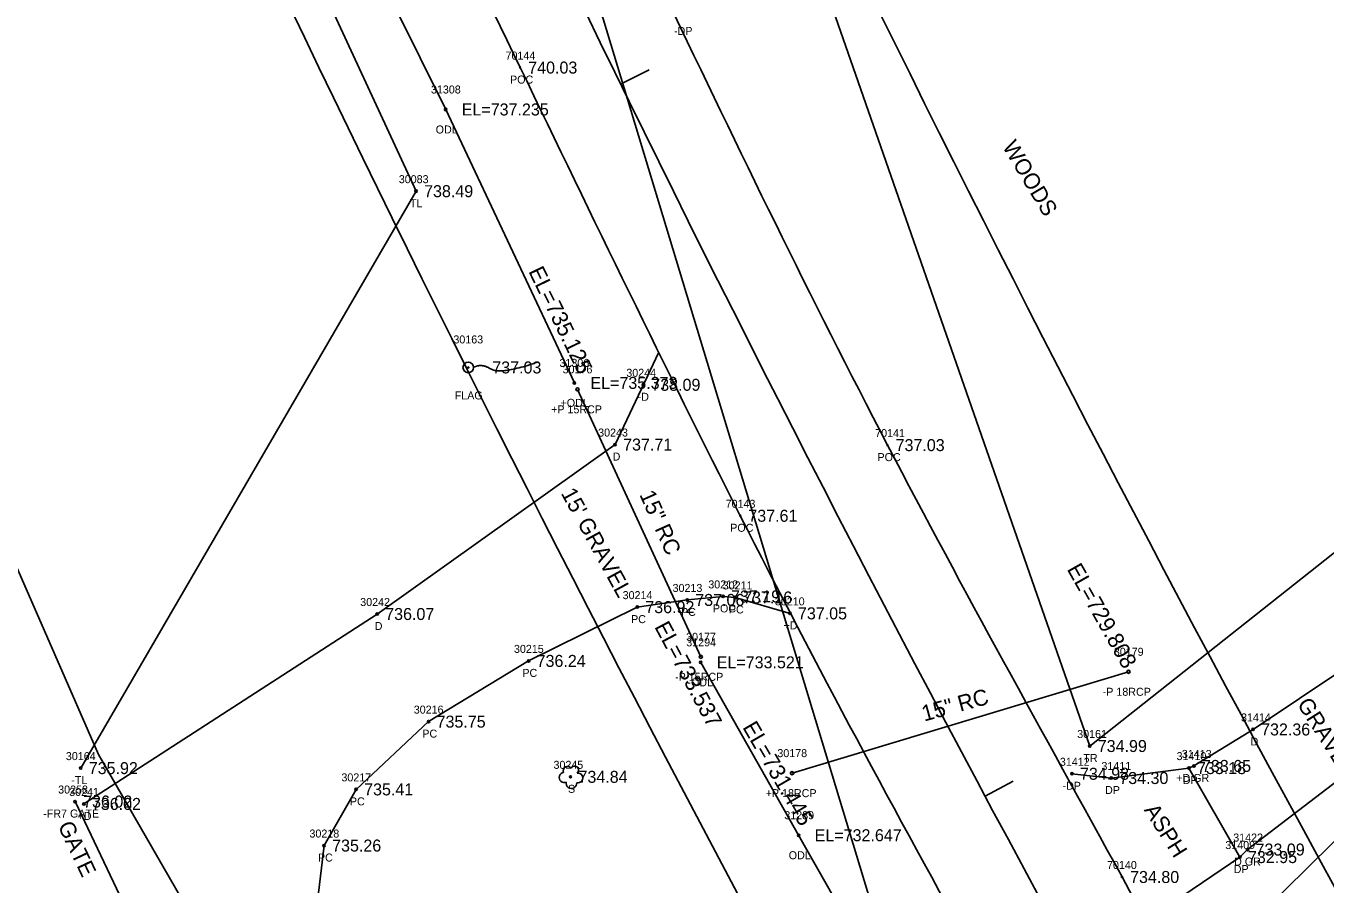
# Model space of a CAD drawing. Extents: x 1375131 to 1378678, y 999028 to 1004053.
# Drawn here: x 1376815.5 to 1376977.9, y 1002369.5 to 1002476.7 of the extents above; entities that cross this region are included whole.
import ezdxf

# ---------------------------------------------------------------- set-up
doc = ezdxf.new("R2010")
doc.units = 0
for name, color, linetype in [('RD_EX_BldgApp_txCode', 7, 'Continuous'), ('RD_EX_DR_Pipe', 7, 'Continuous'), ('RD_EX_DR_Pipe_txCode', 7, 'Continuous'), ('RD_EX_Driveway', 7, 'Continuous'), ('RD_EX_Driveway_txCode', 7, 'Continuous'), ('RD_EX_DV_Prop', 7, 'Continuous'), ('RD_EX_Fence_Other', 7, 'Continuous'), ('RD_EX_Fence_Other_txCode', 7, 'Continuous'), ('RD_EX_H2O', 7, 'Continuous'), ('RD_EX_H2O_txCode', 7, 'Continuous'), ('RD_EX_Road', 7, 'Continuous'), ('RD_EX_Road_txCode', 7, 'Continuous'), ('RD_EX_RW', 7, 'Continuous'), ('RD_EX_SU_Elec', 7, 'Continuous'), ('RD_EX_SU_Telecom', 7, 'Continuous'), ('RD_EX_TX_BldgApp_ELEV', 7, 'Continuous'), ('RD_EX_TX_Driveway_ELEV', 7, 'Continuous'), ('RD_EX_TX_Fence_Other_ELEV', 7, 'Continuous'), ('RD_EX_TX_H2O_ELEV', 7, 'Continuous'), ('RD_EX_TX_Road_ELEV', 7, 'Continuous'), ('RD_EX_TX_VEG_ELEV', 7, 'Continuous'), ('RD_EX_VEG', 7, 'Continuous'), ('RD_EX_VEG_txCode', 7, 'Continuous'), ('RD_HC_Cl', 7, 'Continuous'), ('RD_HC_Data_Tic', 7, 'Continuous'), ('RD_SMD_Locator', 7, 'Continuous'), ('RD_TX_Drainage', 7, 'Continuous'), ('RD_TX_Misc2', 7, 'Continuous'), ('RD_TX_Pipe_ElevEX', 7, 'Continuous')]:
    doc.layers.add(name, color=color, linetype=linetype)

msp = doc.modelspace()

# ---------------------------------------------------------------- linework, layer by layer
at = {"layer": 'RD_EX_DR_Pipe'}
for p, q in [((1376884.43, 1002431.29), (1376899.84, 1002397.86)), ((1376911.24, 1002383.32), (1376953.27, 1002395.99))]:
    msp.add_line(p, q, dxfattribs=at)
at = {"layer": 'RD_EX_Driveway'}
for points in [[(1376822.75, 1002379.47), (1376859.4, 1002403.21), (1376889.13, 1002424.39), (1376894.58, 1002435.93)], [(1376960.83, 1002383.95), (1376961.45, 1002384.22), (1376968.84, 1002388.78), (1376986.2, 1002400.38), (1377021.48, 1002432.82)], [(1377039.21, 1002432.48), (1377014.55, 1002411.97), (1376990.81, 1002391.11), (1376968.15, 1002373.77), (1376967.2, 1002372.83)], [(1376911, 1002403.28), (1376904.12, 1002405.28), (1376902.61, 1002405.41), (1376898.14, 1002404.97), (1376891.9, 1002404.07), (1376878.32, 1002397.35), (1376865.82, 1002389.76), (1376856.77, 1002381.29), (1376852.77, 1002374.27), (1376851.72, 1002365.55), (1376852.45, 1002354.79), (1376854.03, 1002345.76), (1376868.77, 1002323.94), (1376875.45, 1002322.88), (1376882.22, 1002322.93), (1376889.24, 1002324.18), (1376897.79, 1002328.76), (1376900.27, 1002330.09), (1376914.86, 1002340.55), (1376927.38, 1002353.05), (1376934.4, 1002359.99)], [(1376956.44, 1002362.93), (1376956.57, 1002365.63), (1376967.2, 1002372.83), (1376960.83, 1002383.95), (1376951.12, 1002382.71), (1376946.21, 1002383.24)]]:
    msp.add_lwpolyline(points, dxfattribs=at)
at = {"layer": 'RD_EX_DV_Prop'}
msp.add_lwpolyline([(1376724.42, 1002117.06), (1376637.57, 1002230.63), (1376389.38, 1002558.79), (1376664.3, 1002769.81), (1376707.09, 1002654.77), (1376824.56, 1002385.67), (1376921.89, 1002216.69), (1376947.76, 1002098.6)], dxfattribs=at)
at = {"layer": 'RD_EX_Fence_Other'}
msp.add_line((1376828.04, 1002366.35), (1376821.66, 1002379.77), dxfattribs=at)
at = {"layer": 'RD_EX_H2O'}
for points in [[(1376884.04, 1002432.1), (1376867.96, 1002466.27), (1376845.47, 1002511.58), (1376827.22, 1002560.38), (1376806.48, 1002611.18), (1376788.41, 1002651.65), (1376772.82, 1002694.38), (1376753.28, 1002747.21), (1376736.65, 1002792.89), (1376719.2, 1002838.91), (1376701.08, 1002887.18), (1376684.58, 1002932.85), (1376667.2, 1002979.87)], [(1376924.34, 1002353.93), (1376912.06, 1002375.56), (1376899.82, 1002397.17)]]:
    msp.add_lwpolyline(points, dxfattribs=at)
at = {"layer": 'RD_EX_Road'}
for points in [[(1377013.31, 1002264.91), (1376982.81, 1002315.68), (1376952.47, 1002370.34), (1376923.17, 1002424.32), (1376895.64, 1002480.03), (1376870.11, 1002535.05), (1376846.33, 1002588.86), (1376822.29, 1002645.03), (1376786.56, 1002736.46)], [(1376994.75, 1002253.91), (1376964.91, 1002306.46), (1376934.4, 1002359.99), (1376904.77, 1002415.49), (1376877.27, 1002471.51), (1376851.04, 1002526.89), (1376827.48, 1002581.62), (1376804.19, 1002637.82), (1376768.46, 1002728.84)]]:
    msp.add_spline(points, degree=3, dxfattribs=at)
at = {"layer": 'RD_EX_RW'}
for radius in [2767, 2833]:
    msp.add_arc((1379404.86, 1003700.11), radius, 200.26995, 211.13117, dxfattribs=at)
at = {"layer": 'RD_EX_SU_Elec'}
for p, q in [((1376829.24, 1002670.59), (1376932.6, 1002329.07)), ((1376932.6, 1002329.07), (1377119.53, 1002513.39))]:
    msp.add_line(p, q, dxfattribs=at)
at = {"layer": 'RD_EX_SU_Telecom'}
msp.add_circle((1376870.78, 1002434.03), 0.66, dxfattribs=at)
msp.add_open_spline([(1376871.44, 1002434.03), (1376872.44, 1002434.58), (1376874.78, 1002433.1), (1376879.46, 1002434.69)], degree=2, dxfattribs=at)
at = {"layer": 'RD_EX_VEG'}
for points in [[(1376822.36, 1002383.95), (1376864.26, 1002456.06), (1376837.78, 1002513.31), (1376810.93, 1002575.39), (1376788.96, 1002632.35), (1376765.83, 1002686.46), (1376747.01, 1002742.76), (1376726.94, 1002799.92), (1376678.97, 1002911.63), (1376653.9, 1002974.89)], [(1377016.16, 1002440.33), (1376948.43, 1002386.71), (1376912.58, 1002489.62), (1376961.85, 1002505.13), (1376995.25, 1002514.98)]]:
    msp.add_lwpolyline(points, dxfattribs=at)
msp.add_circle((1376883.55, 1002382.86), 0.125, dxfattribs=at)
for centre, radius, start, end in [((1376883.19, 1002383.63), 0.542, 34.9763, 204.756), ((1376884.07, 1002383.71), 0.497, 308.7626, 152.0467), ((1376882.77, 1002382.78), 0.628, 96.4518, 294.734), ((1376884.47, 1002382.72), 0.609, 256.5667, 98.1046), ((1376883.67, 1002382.06), 0.659, 166.8827, 5.7589)]:
    msp.add_arc(centre, radius, start, end, dxfattribs=at)
at = {"layer": 'RD_HC_Cl'}
msp.add_arc((1379404.86, 1003700.11), 2800, 200.26995, 211.13117, dxfattribs=at)
at = {"layer": 'RD_HC_Data_Tic'}
for p, q in [((1376889.81, 1002469.45), (1376893.4, 1002471.21)), ((1376935.35, 1002380.44), (1376938.88, 1002382.32))]:
    msp.add_line(p, q, dxfattribs=at)
at = {"layer": 'RD_SMD_Locator'}
for centre, radius in [((1376877.27, 1002471.51), 0.075), ((1376867.96, 1002466.27), 0.15), ((1376864.26, 1002456.06), 0.15), ((1376870.78, 1002434.03), 0.075), ((1376884.04, 1002432.1), 0.15), ((1376884.43, 1002431.29), 0.2), ((1376892.65, 1002431.86), 0.15), ((1376889.13, 1002424.39), 0.15), ((1376923.17, 1002424.32), 0.075), ((1376904.77, 1002415.49), 0.075), ((1376898.14, 1002404.97), 0.15), ((1376902.61, 1002405.41), 0.15), ((1376904.12, 1002405.28), 0.15), ((1376891.9, 1002404.07), 0.15), ((1376910.97, 1002403.29), 0.15), ((1376859.4, 1002403.21), 0.15), ((1376878.32, 1002397.35), 0.15), ((1376899.84, 1002397.86), 0.2), ((1376899.82, 1002397.17), 0.15), ((1376953.27, 1002395.99), 0.2), ((1376865.82, 1002389.76), 0.15), ((1376968.84, 1002388.78), 0.15), ((1376948.43, 1002386.71), 0.15), ((1376822.36, 1002383.95), 0.15), ((1376960.83, 1002383.95), 0.15), ((1376961.45, 1002384.22), 0.15), ((1376883.55, 1002382.86), 0.075), ((1376911.24, 1002383.32), 0.2), ((1376946.21, 1002383.24), 0.15), ((1376951.12, 1002382.71), 0.15), ((1376856.77, 1002381.29), 0.15), ((1376821.66, 1002379.77), 0.15), ((1376822.75, 1002379.47), 0.15), ((1376852.77, 1002374.27), 0.15), ((1376912.06, 1002375.56), 0.15), ((1376967.2, 1002372.83), 0.15), ((1376968.15, 1002373.77), 0.15), ((1376952.47, 1002370.34), 0.075)]:
    msp.add_circle(centre, radius, dxfattribs=at)

# ---------------------------------------------------------------- texts
at = {"layer": 'RD_EX_BldgApp_txCode'}
for s, p in [('30163', (1376868.92, 1002437.03)), ('FLAG', (1376869.09, 1002430.03))]:
    msp.add_text(s, height=1, dxfattribs=at).set_placement(p)
at = {"layer": 'RD_EX_DR_Pipe_txCode'}
for s, p in [('30176', (1376882.57, 1002433.29)), ('+P 15RCP', (1376881.13, 1002428.29)), ('30177', (1376898, 1002399.86)), ('30179', (1376951.44, 1002397.99)), ('-P 15RCP', (1376896.62, 1002394.86)), ('-P 18RCP', (1376950.05, 1002392.99)), ('30178', (1376909.4, 1002385.32)), ('+P 18RCP', (1376907.94, 1002380.32))]:
    msp.add_text(s, height=1, dxfattribs=at).set_placement(p)
at = {"layer": 'RD_EX_Driveway_txCode'}
for s, p in [('-DP', (1376896.49, 1002475.59)), ('30244', (1376890.53, 1002432.86)), ('-D', (1376891.94, 1002429.86)), ('30243', (1376887.01, 1002425.39)), ('D', (1376888.82, 1002422.39)), ('30213', (1376896.31, 1002405.97)), ('30212', (1376900.77, 1002406.41)), ('30211', (1376902.57, 1002406.28)), ('30242', (1376857.28, 1002404.21)), ('30214', (1376890.07, 1002405.07)), ('30210', (1376909.09, 1002404.29)), ('PC', (1376897.36, 1002402.97)), ('POC', (1376901.34, 1002403.41)), ('PC', (1376903.34, 1002403.28)), ('D', (1376859.09, 1002401.21)), ('PC', (1376891.12, 1002402.07)), ('+D', (1376910.17, 1002401.29)), ('30215', (1376876.49, 1002398.35)), ('PC', (1376877.54, 1002395.35)), ('30216', (1376863.97, 1002390.76)), ('31414', (1376967.33, 1002389.78)), ('PC', (1376865.04, 1002387.76)), ('D', (1376968.53, 1002386.78)), ('31410', (1376959.28, 1002384.95)), ('31413', (1376959.94, 1002385.22)), ('31412', (1376944.7, 1002384.24)), ('31411', (1376949.89, 1002383.71)), ('30217', (1376854.93, 1002382.29)), ('+D GR', (1376959.24, 1002382.22)), ('DP', (1376960.05, 1002381.95)), ('30241', (1376820.92, 1002380.47)), ('-DP', (1376945.02, 1002381.24)), ('DP', (1376950.34, 1002380.71)), ('PC', (1376855.99, 1002379.29)), ('+D', (1376821.96, 1002377.47)), ('30218', (1376850.94, 1002375.27)), ('31422', (1376966.36, 1002374.77)), ('31409', (1376965.37, 1002373.83)), ('PC', (1376852, 1002372.27)), ('-D GR', (1376966.02, 1002371.77)), ('DP', (1376966.42, 1002370.83))]:
    msp.add_text(s, height=1, dxfattribs=at).set_placement(p)
at = {"layer": 'RD_EX_Fence_Other_txCode'}
for s, p in [('30258', (1376819.54, 1002380.77)), ('-FR7 GATE', (1376817.67, 1002377.77))]:
    msp.add_text(s, height=1, dxfattribs=at).set_placement(p)
at = {"layer": 'RD_EX_H2O_txCode'}
for s, p in [('31308', (1376866.12, 1002468.27)), ('ODL', (1376866.71, 1002463.27)), ('31306', (1376882.18, 1002434.1)), ('+ODL', (1376882.31, 1002429.1)), ('31294', (1376898.02, 1002399.17)), ('-ODL', (1376898.16, 1002394.17)), ('31289', (1376910.27, 1002377.56)), ('ODL', (1376910.82, 1002372.56))]:
    msp.add_text(s, height=1, dxfattribs=at).set_placement(p)
at = {"layer": 'RD_EX_Road_txCode'}
for s, p in [('70144', (1376875.44, 1002472.51)), ('POC', (1376876, 1002469.51)), ('70141', (1376921.62, 1002425.32)), ('POC', (1376921.91, 1002422.32)), ('70143', (1376902.94, 1002416.49)), ('POC', (1376903.51, 1002413.49)), ('70140', (1376950.59, 1002371.34))]:
    msp.add_text(s, height=1, dxfattribs=at).set_placement(p)
at = {"layer": 'RD_EX_TX_BldgApp_ELEV'}
msp.add_text('737.03', height=1.5, dxfattribs=at).set_placement((1376873.78, 1002433.28))
at = {"layer": 'RD_EX_TX_Driveway_ELEV'}
for s, p in [('738.09', (1376893.65, 1002431.11)), ('737.71', (1376890.13, 1002423.64)), ('737.06', (1376899.14, 1002404.22)), ('737.19', (1376903.61, 1002404.66)), ('737.16', (1376905.12, 1002404.53)), ('736.07', (1376860.4, 1002402.46)), ('736.92', (1376892.9, 1002403.32)), ('737.05', (1376911.97, 1002402.54)), ('736.24', (1376879.32, 1002396.6)), ('735.75', (1376866.82, 1002389.01)), ('732.36', (1376969.84, 1002388.03)), ('734.98', (1376947.21, 1002382.49)), ('733.18', (1376961.83, 1002383.2)), ('733.65', (1376962.45, 1002383.47)), ('734.30', (1376952.12, 1002381.96)), ('735.41', (1376857.77, 1002380.54)), ('736.02', (1376823.75, 1002378.72)), ('735.26', (1376853.77, 1002373.52)), ('733.09', (1376969.15, 1002373.02)), ('732.95', (1376968.2, 1002372.08))]:
    msp.add_text(s, height=1.5, dxfattribs=at).set_placement(p)
at = {"layer": 'RD_EX_TX_Fence_Other_ELEV'}
msp.add_text('736.02', height=1.5, dxfattribs=at).set_placement((1376822.66, 1002379.02))
at = {"layer": 'RD_EX_TX_H2O_ELEV'}
for s, p in [('EL=737.235', (1376869.96, 1002465.52)), ('EL=735.373', (1376886.04, 1002431.35)), ('EL=733.521', (1376901.82, 1002396.42)), ('EL=732.647', (1376914.06, 1002374.81))]:
    msp.add_text(s, height=1.5, dxfattribs=at).set_placement(p)
at = {"layer": 'RD_EX_TX_Road_ELEV'}
for s, p in [('740.03', (1376878.27, 1002470.76)), ('737.03', (1376924.17, 1002423.57)), ('737.61', (1376905.77, 1002414.74)), ('734.80', (1376953.47, 1002369.59))]:
    msp.add_text(s, height=1.5, dxfattribs=at).set_placement(p)
at = {"layer": 'RD_EX_TX_VEG_ELEV'}
for s, p in [('738.49', (1376865.26, 1002455.31)), ('734.99', (1376949.43, 1002385.96)), ('735.92', (1376823.36, 1002383.2)), ('734.84', (1376884.55, 1002382.11))]:
    msp.add_text(s, height=1.5, dxfattribs=at).set_placement(p)
at = {"layer": 'RD_EX_VEG_txCode'}
for s, p in [('30083', (1376862.1, 1002457.06)), ('TL', (1376863.49, 1002454.06)), ('30161', (1376946.86, 1002387.71)), ('30164', (1376820.5, 1002384.95)), ('TR', (1376947.63, 1002384.71)), ('30245', (1376881.43, 1002383.86)), ('-TL', (1376821.18, 1002381.95)), ('S', (1376883.24, 1002380.86))]:
    msp.add_text(s, height=1, dxfattribs=at).set_placement(p)
at = {"layer": 'RD_TX_Drainage'}
for rotation, p in [(294.0701, (1376892.13, 1002418.15)), (15.2643, (1376927.74, 1002389.76))]:
    msp.add_text('15" RC', height=2, rotation=rotation, dxfattribs=at).set_placement(p)
at = {"layer": 'RD_TX_Misc2'}
for s, rotation, p in [('WOODS', 300.9444, (1376937.45, 1002461.65)), ("15' GRAVEL", 298.7566, (1376882.31, 1002418.31)), ('GRAVEL', 302.2952, (1376974.28, 1002391.96)), ('ASPH', 302.2952, (1376955.15, 1002378.72)), ('GATE', 295.2388, (1376819.46, 1002376.75))]:
    msp.add_text(s, height=2, rotation=rotation, dxfattribs=at).set_placement(p)
at = {"layer": 'RD_TX_Pipe_ElevEX'}
for s, rotation, p in [('EL=735.125', 295.9385, (1376878.26, 1002446.05)), ('EL=729.808', 299.4741, (1376945.53, 1002408.82)), ('EL=733.537', 298.0186, (1376894, 1002401.62)), ('EL=731.445', 300.2241, (1376904.99, 1002389.06))]:
    msp.add_text(s, height=2, rotation=rotation, dxfattribs=at).set_placement(p)

doc.saveas('drawing.dxf')
